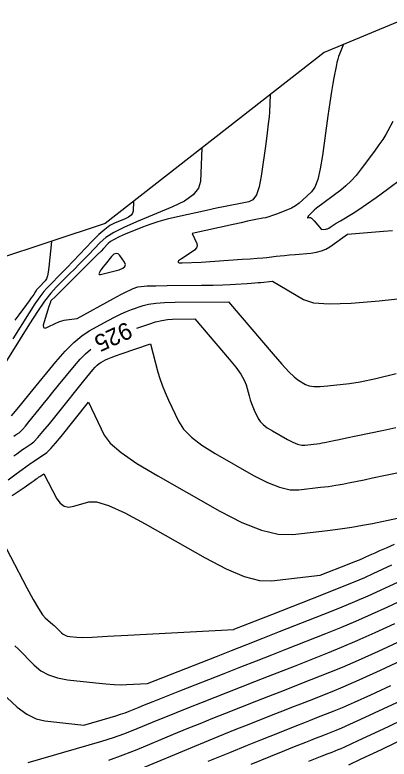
# Model space of a CAD drawing. Extents: x 2175772 to 2185556, y 721391 to 722853.
# Drawn here: x 2178826.6 to 2178888.4, y 722098.3 to 722221.1 of the extents above; entities that cross this region are included whole.
import ezdxf

# ---------------------------------------------------------------- set-up
doc = ezdxf.new("R2010")
doc.units = 0
for name, color, linetype in [('DT_X_Contour_Major', 7, 'Continuous'), ('DT_X_Contour_Minor', 7, 'Continuous'), ('DT_X_TIN_Hull', 7, 'Continuous')]:
    doc.layers.add(name, color=color, linetype=linetype)

msp = doc.modelspace()

# ---------------------------------------------------------------- linework, layer by layer
at = {"layer": 'DT_X_Contour_Major'}
for points in [[(2178846.19, 722190.36), (2178846.12, 722188.75), (2178846.02, 722188.41), (2178845.76, 722188.09), (2178845.35, 722187.79), (2178844.77, 722187.51), (2178843.01, 722186.78), (2178842.29, 722186.39), (2178841.44, 722185.76), (2178840.46, 722184.9), (2178839.35, 722183.79), (2178836.23, 722180.53), (2178835.15, 722179.4), (2178834.25, 722178.48), (2178833.54, 722177.75), (2178833.02, 722177.22), (2178831.86, 722176.07), (2178831.35, 722175.49), (2178830.7, 722174.61), (2178829.9, 722173.44), (2178828.96, 722171.98), (2178826.24, 722167.67)], [(2178846.73, 722169.47), (2178848.68, 722170.13), (2178849.8, 722170.48), (2178850.83, 722170.73), (2178851.76, 722170.89), (2178852.6, 722170.94), (2178856.3, 722170.98), (2178861.98, 722164.33), (2178863.07, 722163), (2178863.9, 722161.85), (2178864.46, 722160.89), (2178864.77, 722160.12), (2178865.25, 722158.3), (2178865.43, 722157.64), (2178865.64, 722157.03), (2178865.85, 722156.46), (2178866.09, 722155.93), (2178866.74, 722154.57), (2178867.06, 722154.06), (2178867.57, 722153.54), (2178868.24, 722153.02), (2178869.09, 722152.49), (2178871.58, 722151.08), (2178872.47, 722150.62), (2178873.25, 722150.31), (2178873.93, 722150.15), (2178874.5, 722150.14), (2178875.9, 722150.31), (2178876.41, 722150.37), (2178876.88, 722150.44), (2178877.31, 722150.51), (2178877.71, 722150.59), (2178878.71, 722150.8), (2178879.25, 722150.91), (2178880.14, 722151.1), (2178881.35, 722151.35), (2178882.9, 722151.68), (2178887.49, 722152.64), (2178889.45, 722153.08)], [(2178826.42, 722151.62), (2178826.63, 722151.77), (2178826.82, 722151.89), (2178827.29, 722152.19), (2178827.52, 722152.39), (2178827.86, 722152.75), (2178828.32, 722153.29), (2178828.9, 722153.99), (2178830.58, 722156.08), (2178831.25, 722156.91), (2178832.01, 722157.85), (2178832.86, 722158.89), (2178833.8, 722160.04), (2178836.41, 722163.23), (2178837.36, 722164.32), (2178838.25, 722165.22), (2178839.07, 722165.92), (2178839.13, 722165.96)], [(2178826.61, 722117.04), (2178827.14, 722116.51), (2178829.78, 722113.83), (2178830.87, 722112.92), (2178832.15, 722112.22), (2178833.62, 722111.73), (2178835.28, 722111.43), (2178839.98, 722110.92), (2178841.61, 722110.76), (2178842.99, 722110.66), (2178844.12, 722110.61), (2178844.99, 722110.63), (2178848.48, 722110.82), (2178859.85, 722115.29), (2178862.33, 722116.26), (2178864.89, 722117.27), (2178867.52, 722118.3), (2178870.24, 722119.37), (2178877.58, 722122.26), (2178880.24, 722123.32), (2178882.68, 722124.33), (2178884.91, 722125.29), (2178886.93, 722126.21), (2178892.04, 722128.59)], [(2178858.5, 722097.98), (2178862.07, 722099.45), (2178864.97, 722100.64), (2178867.19, 722101.54), (2178868.73, 722102.15), (2178871.93, 722103.41), (2178873.12, 722103.88), (2178874.26, 722104.33), (2178875.37, 722104.76), (2178876.45, 722105.19), (2178879.26, 722106.29), (2178880.64, 722106.87), (2178882.66, 722107.76), (2178885.32, 722108.97), (2178888.62, 722110.49)]]:
    msp.add_lwpolyline(points, dxfattribs=at)
at = {"layer": 'DT_X_Contour_Minor'}
for points in [[(2178880.84, 722216.29), (2178880.17, 722214.69), (2178880.03, 722214.3), (2178879.89, 722213.83), (2178879.74, 722213.27), (2178879.6, 722212.62), (2178879.22, 722210.77), (2178879.05, 722209.85), (2178878.84, 722208.5), (2178878.57, 722206.7), (2178878.26, 722204.47), (2178877.35, 722197.93), (2178876.99, 722195.72), (2178876.57, 722193.99), (2178876.09, 722192.74), (2178875.56, 722191.97), (2178874.08, 722190.56), (2178873.51, 722190.06), (2178872.91, 722189.63), (2178872.27, 722189.27), (2178871.59, 722188.97), (2178869.76, 722188.26), (2178869.1, 722188.02), (2178868.51, 722187.83), (2178867.98, 722187.68), (2178867.51, 722187.58), (2178866.36, 722187.37), (2178865.8, 722187.26), (2178864.99, 722187.09), (2178863.92, 722186.86), (2178862.6, 722186.57), (2178855.85, 722185.09), (2178856.6, 722183.42), (2178856.67, 722183.06), (2178856.54, 722182.69), (2178856.22, 722182.31), (2178855.7, 722181.93), (2178854.07, 722180.91), (2178853.62, 722180.58), (2178853.49, 722180.35), (2178853.68, 722180.23), (2178854.19, 722180.21), (2178857.33, 722180.35), (2178864.1, 722180.82), (2178865.45, 722180.91), (2178866.58, 722181), (2178867.49, 722181.07), (2178868.18, 722181.14), (2178869.74, 722181.31), (2178870.38, 722181.38), (2178871.1, 722181.45), (2178871.93, 722181.53), (2178872.85, 722181.61), (2178875.42, 722181.84), (2178876.35, 722181.97), (2178877.18, 722182.19), (2178877.93, 722182.5), (2178878.59, 722182.9), (2178881.47, 722184.98), (2178887.42, 722185.44), (2178888.9, 722185.59)], [(2178868.73, 722208), (2178868.61, 722205.11), (2178868.55, 722204.31), (2178868.42, 722203.18), (2178868.24, 722201.7), (2178867.99, 722199.87), (2178867.23, 722194.55), (2178866.89, 722192.78), (2178866.45, 722191.48), (2178865.89, 722190.65), (2178865.21, 722190.29), (2178863.27, 722189.93), (2178862.41, 722189.77), (2178861.29, 722189.54), (2178859.89, 722189.24), (2178858.23, 722188.88), (2178853.43, 722187.82), (2178851.72, 722187.42), (2178850.19, 722187), (2178848.84, 722186.58), (2178847.67, 722186.13), (2178844.77, 722184.94), (2178843.78, 722184.51), (2178842.99, 722184.11), (2178842.4, 722183.75), (2178842.01, 722183.42), (2178841.22, 722182.6), (2178840.81, 722182.18), (2178840.17, 722181.53), (2178839.3, 722180.67), (2178838.21, 722179.58), (2178834.98, 722176.37), (2178833.93, 722175.32), (2178833.17, 722174.56), (2178832.71, 722174.1), (2178832.54, 722173.94), (2178832.49, 722173.86), (2178832.48, 722173.81), (2178832.45, 722173.72), (2178832.36, 722173.45), (2178832.22, 722173), (2178831.41, 722170.5), (2178831.28, 722169.92), (2178831.33, 722169.57), (2178831.57, 722169.46), (2178831.99, 722169.59), (2178833.36, 722170.25), (2178833.86, 722170.47), (2178834.32, 722170.64), (2178834.74, 722170.76), (2178835.13, 722170.83), (2178836.85, 722171.04), (2178842.89, 722174.35), (2178844.06, 722174.98), (2178844.98, 722175.46), (2178845.66, 722175.79), (2178846.09, 722175.97), (2178846.9, 722176.25), (2178847.43, 722176.34), (2178848.41, 722176.41), (2178849.85, 722176.46), (2178851.73, 722176.5), (2178857.37, 722176.55), (2178859.31, 722176.57), (2178860.89, 722176.6), (2178862.13, 722176.64), (2178863.02, 722176.69), (2178864.91, 722176.82), (2178865.59, 722176.86), (2178866.19, 722176.91), (2178866.72, 722176.96), (2178867.17, 722177), (2178869.12, 722177.22), (2178874.25, 722174.16), (2178875.85, 722173.65), (2178878.46, 722173.45), (2178882.08, 722173.56), (2178886.7, 722173.97), (2178900.37, 722175.46)], [(2178888.99, 722203.54), (2178888.17, 722202.02), (2178887.8, 722201.39), (2178887.31, 722200.61), (2178886.68, 722199.71), (2178885.93, 722198.67), (2178883.74, 722195.72), (2178882.92, 722194.67), (2178882.09, 722193.74), (2178881.24, 722192.93), (2178880.38, 722192.23), (2178876.36, 722189.26), (2178875.99, 722188.91), (2178875.9, 722188.83), (2178875.79, 722188.72), (2178875.66, 722188.58), (2178875.5, 722188.42), (2178875.06, 722187.97), (2178874.93, 722187.82), (2178874.87, 722187.72), (2178874.88, 722187.68), (2178874.95, 722187.68), (2178875.23, 722187.74), (2178875.36, 722187.73), (2178875.52, 722187.63), (2178875.72, 722187.45), (2178875.96, 722187.18), (2178877.18, 722185.74), (2178877.9, 722185.81), (2178878.05, 722185.83), (2178878.18, 722185.86), (2178878.29, 722185.9), (2178878.38, 722185.95), (2178878.6, 722186.11), (2178878.77, 722186.23), (2178879.12, 722186.44), (2178879.64, 722186.76), (2178880.34, 722187.18), (2178882.44, 722188.44), (2178883.38, 722189.04), (2178884.64, 722189.9), (2178886.2, 722191.02), (2178888.08, 722192.39), (2178897.55, 722199.41)], [(2178857.46, 722199.18), (2178857.22, 722193.68), (2178856.89, 722192.54), (2178856.02, 722191.45), (2178854.6, 722190.43), (2178852.63, 722189.47), (2178846.64, 722187), (2178844.58, 722186.09), (2178842.9, 722185.22), (2178841.6, 722184.39), (2178840.68, 722183.61), (2178838.72, 722181.56), (2178837.98, 722180.79), (2178837.21, 722180), (2178836.42, 722179.21), (2178835.61, 722178.4), (2178833.42, 722176.22), (2178832.53, 722175.23), (2178831.49, 722173.89), (2178830.32, 722172.2), (2178828.99, 722170.17), (2178822.49, 722159.84)], [(2178832.65, 722183.77), (2178832.22, 722179.54), (2178832.11, 722178.71), (2178831.97, 722178.06), (2178831.79, 722177.57), (2178831.58, 722177.24), (2178830.6, 722176.23), (2178830.42, 722176.04), (2178830.3, 722175.92), (2178830.24, 722175.85), (2178830.17, 722175.76), (2178830.09, 722175.64), (2178829.99, 722175.48), (2178829.7, 722175.02), (2178829.55, 722174.79), (2178829.3, 722174.44), (2178828.96, 722173.97), (2178828.52, 722173.38), (2178827.24, 722171.64), (2178826.56, 722170.79)], [(2178843.78, 722179.1), (2178844.39, 722179.33), (2178844.74, 722179.61), (2178844.83, 722179.94), (2178844.68, 722180.32), (2178843.92, 722181.42), (2178843.62, 722181.72), (2178843.29, 722181.79), (2178842.93, 722181.64), (2178842.55, 722181.26), (2178841.48, 722179.96), (2178841.13, 722179.51), (2178840.86, 722179.16), (2178840.68, 722178.9), (2178840.59, 722178.74), (2178840.46, 722178.41), (2178840.51, 722178.33), (2178840.75, 722178.33), (2178841.19, 722178.41), (2178841.83, 722178.57), (2178843.78, 722179.1)], [(2178826.05, 722154.96), (2178826.71, 722155.76), (2178827.73, 722157.01), (2178829.13, 722158.72), (2178833.35, 722163.87), (2178834.88, 722165.64), (2178836.31, 722167.09), (2178837.64, 722168.21), (2178838.87, 722169.02), (2178842, 722170.73), (2178843.12, 722171.33), (2178844.13, 722171.82), (2178845.03, 722172.22), (2178845.83, 722172.52), (2178847.79, 722173.19), (2178848.67, 722173.41), (2178849.84, 722173.57), (2178851.29, 722173.68), (2178853.03, 722173.73), (2178861.83, 722173.81), (2178869.2, 722165.18), (2178870.65, 722163.53), (2178871.81, 722162.27), (2178872.7, 722161.4), (2178873.31, 722160.92), (2178874.56, 722160.17), (2178875.14, 722159.95), (2178875.94, 722159.83), (2178876.97, 722159.81), (2178878.21, 722159.91), (2178881.81, 722160.3), (2178883.57, 722160.59), (2178886.15, 722161.15), (2178889.54, 722161.98)], [(2178826.41, 722148.36), (2178826.93, 722148.74), (2178827.43, 722149.11), (2178827.63, 722149.25), (2178827.86, 722149.42), (2178828.14, 722149.6), (2178828.44, 722149.8), (2178829.3, 722150.36), (2178829.73, 722150.72), (2178830.37, 722151.4), (2178831.22, 722152.38), (2178832.28, 722153.68), (2178835.38, 722157.54), (2178836.45, 722158.86), (2178837.32, 722159.94), (2178837.99, 722160.77), (2178838.46, 722161.36), (2178839.47, 722162.59), (2178839.84, 722163.01), (2178840.18, 722163.35), (2178840.49, 722163.62), (2178840.79, 722163.81), (2178841.53, 722164.22), (2178841.91, 722164.4), (2178842.47, 722164.63), (2178843.22, 722164.9), (2178844.15, 722165.23), (2178848.95, 722166.86), (2178850.18, 722162.18), (2178850.49, 722161.13), (2178850.89, 722160.02), (2178851.38, 722158.83), (2178851.95, 722157.56), (2178853.6, 722154.09), (2178854.44, 722152.78), (2178855.73, 722151.46), (2178857.46, 722150.13), (2178859.63, 722148.78), (2178866, 722145.16), (2178868.26, 722144), (2178870.26, 722143.21), (2178872, 722142.8), (2178873.47, 722142.77), (2178877.05, 722143.19), (2178878.35, 722143.35), (2178879.55, 722143.53), (2178880.65, 722143.71), (2178881.66, 722143.91), (2178884.23, 722144.45), (2178885.6, 722144.74), (2178887.77, 722145.19), (2178890.75, 722145.82)], [(2178825.51, 722144.43), (2178826.82, 722145.4), (2178827.78, 722146.11), (2178828.4, 722146.57), (2178828.67, 722146.77), (2178828.93, 722146.96), (2178829.07, 722147.06), (2178829.31, 722147.22), (2178829.64, 722147.43), (2178830.06, 722147.71), (2178831.32, 722148.53), (2178831.85, 722148.94), (2178832.51, 722149.59), (2178833.3, 722150.46), (2178834.21, 722151.56), (2178838.76, 722157.22), (2178841.35, 722151.77), (2178842.32, 722150.47), (2178844.11, 722148.92), (2178846.73, 722147.12), (2178850.16, 722145.07), (2178860.42, 722139.25), (2178864.06, 722137.37), (2178867.28, 722136.1), (2178870.07, 722135.45), (2178872.44, 722135.4), (2178878.2, 722136.07), (2178880.29, 722136.34), (2178882.22, 722136.62), (2178883.99, 722136.92), (2178885.62, 722137.23), (2178889.75, 722138.1)], [(2178826.17, 722141.82), (2178828.1, 722143.15), (2178829.3, 722143.99), (2178829.79, 722144.33), (2178830.13, 722144.59), (2178830.25, 722144.67), (2178830.33, 722144.73), (2178830.38, 722144.77), (2178830.41, 722144.79), (2178830.43, 722144.81), (2178830.45, 722144.82), (2178830.51, 722144.86), (2178830.6, 722144.92), (2178830.72, 722144.99), (2178831.35, 722145.41), (2178833.53, 722141.28), (2178834.06, 722140.55), (2178834.7, 722140.1), (2178835.45, 722139.94), (2178836.32, 722140.08), (2178838.79, 722140.82), (2178840.07, 722140.8), (2178842.04, 722140.19), (2178844.72, 722138.97), (2178848.09, 722137.16), (2178858.01, 722131.54), (2178861.48, 722129.72), (2178864.46, 722128.48), (2178866.94, 722127.81), (2178868.92, 722127.73), (2178877, 722128.68), (2178881.75, 722130.55), (2178882.69, 722130.92), (2178883.46, 722131.23), (2178884.08, 722131.49), (2178884.53, 722131.69), (2178885.53, 722132.16), (2178886.05, 722132.39), (2178886.84, 722132.74), (2178887.9, 722133.2), (2178889.24, 722133.78)], [(2178823.11, 722136.92), (2178828.56, 722126.62), (2178829.62, 722124.65), (2178830.48, 722123.17), (2178831.13, 722122.16), (2178831.57, 722121.64), (2178832.47, 722120.9), (2178832.79, 722120.63), (2178833.09, 722120.36), (2178833.37, 722120.1), (2178833.63, 722119.84), (2178834.29, 722119.17), (2178834.56, 722118.95), (2178834.88, 722118.77), (2178835.25, 722118.65), (2178835.66, 722118.58), (2178836.83, 722118.45), (2178837.68, 722118.43), (2178839.37, 722118.48), (2178841.88, 722118.6), (2178845.22, 722118.77), (2178862.74, 722119.75), (2178862.79, 722119.77), (2178863.18, 722119.92), (2178864.35, 722120.38), (2178866.29, 722121.14), (2178869, 722122.21), (2178877.25, 722125.45), (2178880.1, 722126.58), (2178882.46, 722127.54), (2178884.34, 722128.33), (2178885.73, 722128.95), (2178888.79, 722130.37)], [(2178825.28, 722108.48), (2178826.97, 722106.92), (2178828.57, 722105.77), (2178830.09, 722105.01), (2178831.52, 722104.66), (2178837.99, 722103.96), (2178842.34, 722105.2), (2178843.23, 722105.46), (2178844.04, 722105.73), (2178844.78, 722105.98), (2178845.43, 722106.24), (2178847.08, 722106.92), (2178847.97, 722107.28), (2178849.39, 722107.85), (2178851.34, 722108.62), (2178853.82, 722109.6), (2178861.15, 722112.48), (2178863.86, 722113.54), (2178866.48, 722114.57), (2178869.02, 722115.57), (2178871.48, 722116.53), (2178877.92, 722119.07), (2178880.37, 722120.05), (2178882.89, 722121.12), (2178885.47, 722122.25), (2178888.13, 722123.47), (2178895.29, 722126.8)], [(2178828.76, 722097.77), (2178838.87, 722100.67), (2178840.95, 722101.28), (2178842.85, 722101.89), (2178844.56, 722102.5), (2178846.09, 722103.1), (2178849.94, 722104.69), (2178851.5, 722105.32), (2178853.28, 722106.04), (2178855.3, 722106.85), (2178857.55, 722107.73), (2178863.85, 722110.21), (2178866.17, 722111.12), (2178868.43, 722112.01), (2178870.61, 722112.87), (2178872.72, 722113.7), (2178878.26, 722115.87), (2178880.5, 722116.79), (2178883.1, 722117.9), (2178886.04, 722119.21), (2178889.32, 722120.72)], [(2178842.08, 722098.19), (2178844.45, 722099.04), (2178846.75, 722099.95), (2178852.79, 722102.45), (2178855.02, 722103.37), (2178857.18, 722104.24), (2178859.26, 722105.08), (2178861.27, 722105.87), (2178866.54, 722107.94), (2178868.49, 722108.71), (2178870.37, 722109.45), (2178872.2, 722110.17), (2178873.96, 722110.86), (2178878.59, 722112.68), (2178880.64, 722113.52), (2178883.31, 722114.69), (2178886.6, 722116.17), (2178890.52, 722117.98)], [(2178847.41, 722096.81), (2178855.65, 722100.21), (2178858.55, 722101.41), (2178861.07, 722102.44), (2178863.22, 722103.31), (2178865, 722104.01), (2178869.24, 722105.68), (2178870.8, 722106.29), (2178872.32, 722106.89), (2178873.79, 722107.47), (2178875.21, 722108.02), (2178878.93, 722109.49), (2178880.75, 722110.24), (2178883.41, 722111.42), (2178886.93, 722113.02), (2178891.29, 722115.04)], [(2178865.6, 722097.49), (2178868.86, 722098.83), (2178871.15, 722099.77), (2178872.45, 722100.29), (2178874.63, 722101.15), (2178875.43, 722101.46), (2178876.21, 722101.77), (2178876.96, 722102.06), (2178877.69, 722102.35), (2178879.6, 722103.1), (2178880.53, 722103.49), (2178881.9, 722104.09), (2178883.71, 722104.91), (2178885.94, 722105.95), (2178892.49, 722109)], [(2178875.11, 722098), (2178876.18, 722098.43), (2178877.32, 722098.88), (2178877.74, 722099.05), (2178878.15, 722099.21), (2178878.93, 722099.51), (2178879.94, 722099.91), (2178880.43, 722100.11), (2178881.15, 722100.43), (2178882.09, 722100.86), (2178883.27, 722101.4), (2178886.71, 722103.01), (2178888.34, 722103.77), (2178890.64, 722104.86)], [(2178881.7, 722097.38), (2178883.76, 722098.36), (2178887.11, 722099.95), (2178891.74, 722102.16)]]:
    msp.add_lwpolyline(points, dxfattribs=at)
at = {"layer": 'DT_X_TIN_Hull'}
msp.add_lwpolyline([(2179107.62, 722089.39), (2179075.12, 722109.69), (2179069.22, 722113.13), (2179059.79, 722118.52), (2179054.81, 722121.98), (2179049.44, 722125.39), (2179049.52, 722126.42), (2178984.03, 722166.57), (2178919.21, 722205.54), (2178909.71, 722210.4), (2178906.79, 722212.51), (2178903.07, 722214.83), (2178899.76, 722216.57), (2178897.01, 722218.1), (2178892.62, 722221.15), (2178877.64, 722214.96), (2178841.51, 722186.7), (2178759.74, 722159.66), (2178721.08, 722141.18), (2178706.95, 722109.71), (2178684.5, 722059.42)], dxfattribs=at)

# ---------------------------------------------------------------- texts
at = {"layer": 'DT_X_Contour_Major'}
msp.add_text('925', height=2.8, rotation=204.7904, dxfattribs=at).set_placement((2178845.1, 722170.59))

doc.saveas('drawing.dxf')
